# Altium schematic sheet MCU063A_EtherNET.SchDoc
size 431 x 279 mm; Date: Not shown in title block; ApprovedBy: Not shown in title block; CheckedBy: Not shown in title block; Author: Not shown in title block; CompanyName: Not shown in title block; Engineer: Not shown in title block; Organization: Not shown in title block; Address1: Not shown in title block; Address2: Not shown in title block; Address3: Not shown in title block; Address4: Not shown in title block; DocumentNumber: 7; Revision: Use project parameter SCH_Rev; SheetNumber: 7; SheetTotal: 11; PageSetup: Record=PageOptions¦CenterHorizontal=True¦CenterVertical=True¦PrintScale=1.00¦XCorrection=1.00¦YCorrection=1.00¦PrintKind=0¦BorderSize=5000000¦LeftOffset=0¦BottomOffset=0¦Orientation=2¦PaperLength=1000¦PaperWidth=1000¦Scale=100¦PaperSource=15¦PrintQuality=600¦MediaType=1¦DitherType=10¦PaperKind=Letter¦PrintScaleMode=1
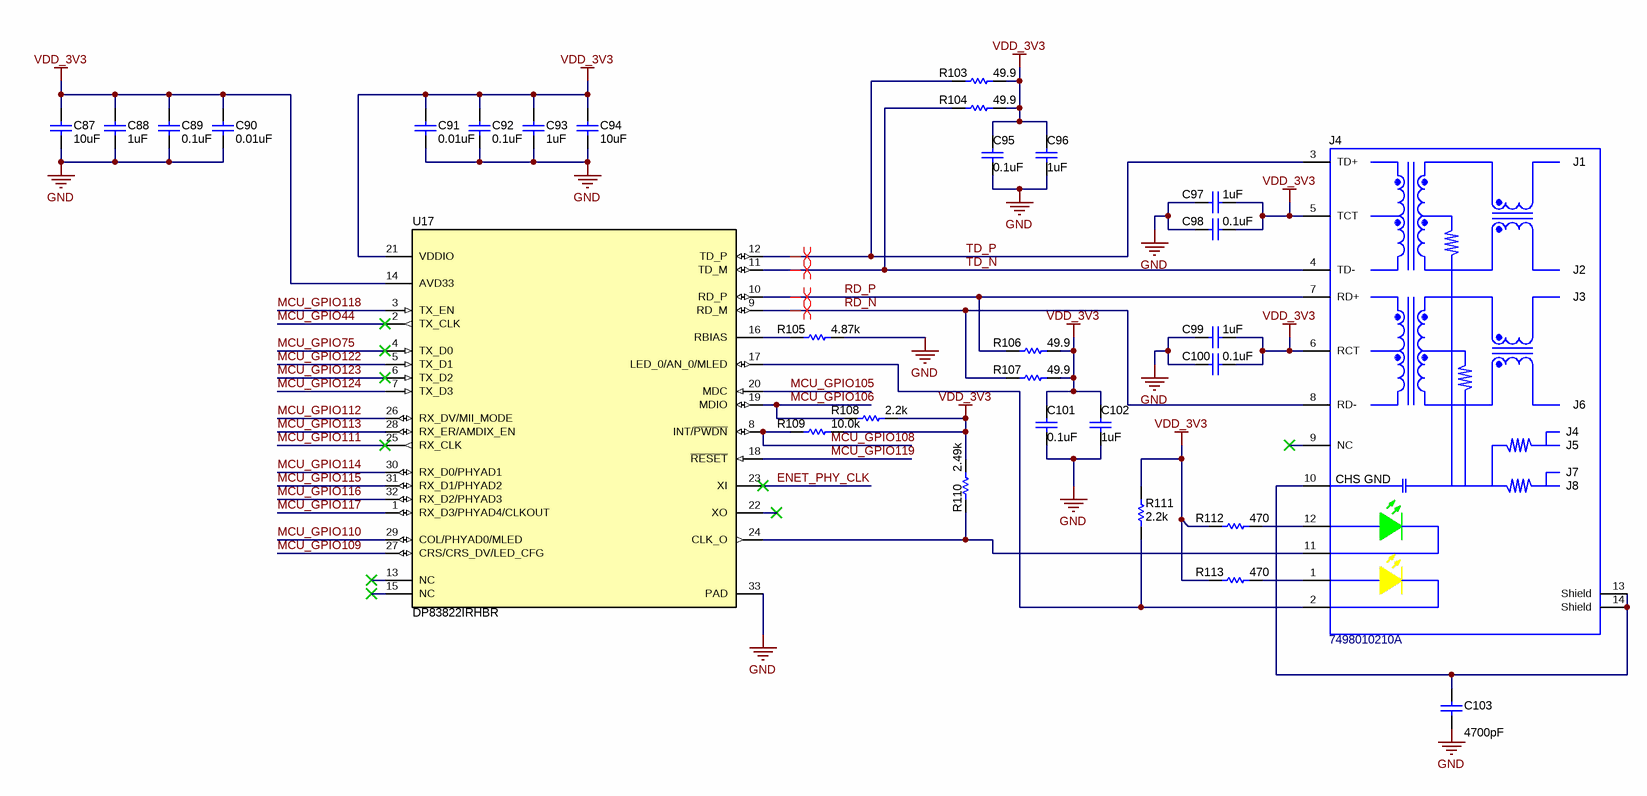
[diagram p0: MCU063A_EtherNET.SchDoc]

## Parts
C87  ValueDisplayed: 10uF  [0402]  (hidden comment: CL05A106MQ5NUNC)
C88  ValueDisplayed: 1uF  [0402]  (hidden comment: EMK105BJ105KVHF)
C89  ValueDisplayed: 0.1uF  [0402]  (hidden comment: LMK105BJ104KV-F)
C90  ValueDisplayed: 0.01uF  [0402]  (hidden comment: 885012205031)
C91  ValueDisplayed: 0.01uF  [0402]  (hidden comment: 885012205031)
C92  ValueDisplayed: 0.1uF  [0402]  (hidden comment: LMK105BJ104KV-F)
C93  ValueDisplayed: 1uF  [0402]  (hidden comment: EMK105BJ105KVHF)
C94  ValueDisplayed: 10uF  [0402]  (hidden comment: CL05A106MQ5NUNC)
C95  ValueDisplayed: 0.1uF  [0402]  (hidden comment: LMK105BJ104KV-F)
C96  ValueDisplayed: 1uF  [0402]  (hidden comment: EMK105BJ105KVHF)
C97  ValueDisplayed: 1uF  [0402]  (hidden comment: EMK105BJ105KVHF)
C98  ValueDisplayed: 0.1uF  [0402]  (hidden comment: LMK105BJ104KV-F)
C99  ValueDisplayed: 1uF  [0402]  (hidden comment: EMK105BJ105KVHF)
C100  ValueDisplayed: 0.1uF  [0402]  (hidden comment: LMK105BJ104KV-F)
C101  ValueDisplayed: 0.1uF  [0402]  (hidden comment: LMK105BJ104KV-F)
C102  ValueDisplayed: 1uF  [0402]  (hidden comment: EMK105BJ105KVHF)
C103  ValueDisplayed: 4700pF  [1206]  (hidden comment: 12061C472KAT2A)
J4  7498010210A  [Wurth_7498010210A]
R103  ValueDisplayed: 49.9  [0402]  (hidden comment: RC0402FR-0749R9L)
R104  ValueDisplayed: 49.9  [0402]  (hidden comment: RC0402FR-0749R9L)
R105  ValueDisplayed: 4.87k  [0402]  (hidden comment: CRCW04024K87FKED)
R106  ValueDisplayed: 49.9  [0402]  (hidden comment: RC0402FR-0749R9L)
R107  ValueDisplayed: 49.9  [0402]  (hidden comment: RC0402FR-0749R9L)
R108  ValueDisplayed: 2.2k  [0402]  (hidden comment: CRCW04022K20JNED)
R109  ValueDisplayed: 10.0k  [0402]  (hidden comment: RC0402FR-0710KL)
R110  ValueDisplayed: 2.49k  [0402]  (hidden comment: CRCW04022K49FKED)
R111  ValueDisplayed: 2.2k  [0402]  (hidden comment: CRCW04022K20JNED)
R112  ValueDisplayed: 470  [0603]  (hidden comment: CRCW0603470RJNEA)
R113  ValueDisplayed: 470  [0603]  (hidden comment: CRCW0603470RJNEA)
U17  DP83822IRHBR  [RHB0032B]

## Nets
GND: C87.2 C88.2 C89.2 C90.2 C91.2 C92.2 C93.2 C94.2 C95.2 C96.2 C97.1 C98.1 C99.1 C100.1 C101.2 C102.2 C103.1 R105.2 U17.33(PAD)
VDD_3V3: C87.1 C88.1 C89.1 C90.1 C91.1 C92.1 C93.1 C94.1 C95.1 C96.1 C97.2 C98.2 C99.2 C100.2 C101.1 C102.1 J4.5(TCT) J4.6(RCT) R103.2 R104.2 R106.2 R107.2 R108.1 R109.2 R110.2 R111.2 R112.1 R113.1 U17.14(AVD33) U17.21(VDDIO)
ENET_PHY_CLK: U17.23(XI)
MCU_GPIO44: U17.2(TX_CLK)
MCU_GPIO75: U17.4(TX_D0)
MCU_GPIO105: U17.20(MDC)
MCU_GPIO106: R108.2 U17.19(MDIO)
MCU_GPIO108: R109.1 U17.8(INT/~{PWDN})
MCU_GPIO109: U17.27(CRS/CRS_DV/LED_CFG)
MCU_GPIO110: U17.29(COL/PHYAD0/MLED)
MCU_GPIO111: U17.25(RX_CLK)
MCU_GPIO112: U17.26(RX_DV/MII_MODE)
MCU_GPIO113: U17.28(RX_ER/AMDIX_EN)
MCU_GPIO114: U17.30(RX_D0/PHYAD1)
MCU_GPIO115: U17.31(RX_D1/PHYAD2)
MCU_GPIO116: U17.32(RX_D2/PHYAD3)
MCU_GPIO117: U17.1(RX_D3/PHYAD4/CLKOUT)
MCU_GPIO118: U17.3(TX_EN)
MCU_GPIO119: U17.18(~{RESET})
MCU_GPIO122: U17.5(TX_D1)
MCU_GPIO123: U17.6(TX_D2)
MCU_GPIO124: U17.7(TX_D3)
RD_N: J4.8(RD-) R107.1 U17.9(RD_M)
RD_P: J4.7(RD+) R106.1 U17.10(RD_P)
TD_N: J4.4(TD-) R104.1 U17.11(TD_M)
TD_P: J4.3(TD+) R103.1 U17.12(TD_P)
NetC103_2: C103.2 J4.10(CHS_GND) J4.13(Shield) J4.14(Shield)
NetJ4_1: J4.1(RIGHT_LED_ANODE) R113.2
NetJ4_2: J4.2(RIGHT_LED_CATHODE) R111.1 U17.17(LED_0/AN_0/MLED)
NetJ4_11: J4.11(LEFT_LED_CATHODE) R110.1 U17.24(CLK_O)
NetJ4_12: J4.12(LEFT_LED_ANODE) R112.2
NetR105_1: R105.1 U17.16(RBIAS)

Not connected (* = marked no-connect by the designer): J4 9(NC)*; U17 13(NC)* 15(NC)* 22(XO)*

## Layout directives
differential pair: RD_N, RD_P, TD_N, TD_P

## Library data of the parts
C87 C94 = CMP-0006340-2: CAP, CERM, 10 uF, 6.3 V, +/- 20%, X5R, 0402; Manufacturer: Samsung Electro-Mechanics; TaMin_C: -55°C; Polarized: N; SizeAreaWB_mm2: 3; Value1: Unknown; U/M: EA; Value: 10uF; TaMax_C: 85°C; SizeZ_mm: 0.6; SizeX_mm: 1; SizeY_mm: 0.5; Value2: 6.3V; Cap_F: 10µF; AEC Category: Q200
C88 C93 C96 C97 C99 C102 = CMP-0006347-2: CAP, CERM, 1 uF, 16 V, +/- 10%, X5R, 0402; Manufacturer: Taiyo Yuden; TaMin_C: -55°C; Polarized: N; SizeAreaWB_mm2: 3; Value1: Unknown; U/M: EA; Value: 1uF; TaMax_C: 85°C; SizeZ_mm: 0.6; SizeX_mm: 1; SizeY_mm: 0.5; Value2: 16V; Cap_F: 1µF; AEC Category: Q200
C89 C92 C95 C98 C100 C101 = CMP-0064930-2: CAP, CERM, 0.1 uF, 10 V,+/- 10%, X5R, 0402; Manufacturer: Taiyo Yuden; TaMin_C: -55°C; Polarized: N; SizeAreaWB_mm2: 3; Value1: Unknown; U/M: EA; Value: 0.1uF; TaMax_C: 85°C; SizeZ_mm: 0.6; SizeX_mm: 1; SizeY_mm: 0.5; Value2: 10V; Cap_F: 100nF; AEC Category: Q200
C90 C91 = CMP-0006227-2: CAP, CERM, 0.01 uF, 16 V, +/- 10%, X7R, 0402; Manufacturer: Wurth Elektronik; TaMin_C: -55°C; Polarized: N; SizeAreaWB_mm2: 3; Value1: Unknown; U/M: EA; Value: 0.01uF; TaMax_C: 125°C; SizeZ_mm: 0.6; SizeX_mm: 1; SizeY_mm: 0.5; Value2: 16V; Cap_F: 10nF; AEC Category: Q200
C103 = CMP-0008501-2: CAP, CERM, 4700 pF, 100 V, +/- 10%, X7R, 1206; Manufacturer: AVX; TaMin_C: -55°C; ESR_ohm: 1.78d; Polarized: N; SizeAreaWB_mm2: 10.92; Value1: 0.178 ohm; U/M: EA; Value: 4700pF; TaMax_C: 125°C; SizeZ_mm: 1.35; SizeX_mm: 3.2; SizeY_mm: 1.6; Value2: 100V; SizeArea_mm2: 5.12; Cap_F: 4.7nF; AEC Category: Q200
J4 = CMP-0086350-1: Connector, RJ45, 1x1, Gold, R/A, SMT; Manufacturer: Wurth Elektronik; Row_Count: 1; Gender: Female
R103 R104 R106 R107 = CMP-0026738-1: RES, 49.9, 1%, 0.063 W, 0402; Manufacturer: Yageo America; Power_W: 63mW; TempCo: 100 ppm/C; Value_Code: 49R9; U/M: EA; Value: 49.9; EIA_Code: E96; SizeX_mm: 1; SizeY_mm: 0.5; SizeZ_mm: 0.6; Value2: 0.063W; AEC Qualified: N; VDC_V: 50V; AEC Category: Q200
R105 = CMP-0026413-2: RES, 4.87 k, 1%, 0.063 W, AEC-Q200 Grade 0, 0402; Manufacturer: Vishay-Dale; Power_W: 63mW; TempCo: 100 ppm/C; Value_Code: 4k87; Value: 4.87k; EIA_Code: E96; SizeX_mm: 1; SizeY_mm: 0.5; SizeZ_mm: 0.6; Value2: 0.063W; AEC Qualified: Y; VDC_V: 50V; AEC Category: Q200; AEC Grade: 0
R108 R111 = CMP-0026890-5: RES, 2.2 k, 5%, 0.063 W, AEC-Q200 Grade 0, 0402; Manufacturer: Vishay-Dale; Power_W: 63mW; TempCo: 200 ppm/C; Value_Code: 2k20; Value: 2.2k; EIA_Code: E24; SizeX_mm: 1; SizeY_mm: 0.5; SizeZ_mm: 0.6; Value2: 0.063W; AEC Qualified: Y; VDC_V: 50V; AEC Category: Q200; AEC Grade: 0
R109 = CMP-0078669-1: RES, 10.0 k, 1%, 0.063 W, 0402; Manufacturer: Yageo America; Power_W: 63mW; Green_Lifecycle: Active; TempCo: 100 ppm/C; Value_Code: 10k0; Green_REACh: Passed; Value: 10.0k; EIA_Code: E96; Res_ohm: 10k; SizeX_mm: 1; SizeY_mm: 0.5; SizeZ_mm: 0.6; Value2: 0.063W; AEC Qualified: N; AEC Category: Q200
R110 = CMP-0026237-2: RES, 2.49 k, 1%, 0.063 W, AEC-Q200 Grade 0, 0402; Manufacturer: Vishay-Dale; Power_W: 63mW; TempCo: 100 ppm/C; Value_Code: 2k49; Value: 2.49k; EIA_Code: E96; SizeX_mm: 1; SizeY_mm: 0.5; SizeZ_mm: 0.6; Value2: 0.063W; AEC Qualified: Y; VDC_V: 50V; AEC Category: Q200; AEC Grade: 0
R112 R113 = CMP-0025813-4: RES, 470, 5%, 0.1 W, AEC-Q200 Grade 0, 0603; Manufacturer: Vishay-Dale; Power_W: 100mW; TempCo: 200 ppm/C; Value_Code: 470R; Value: 470; EIA_Code: E24; SizeX_mm: 1.6; SizeY_mm: 0.8; SizeZ_mm: 1; Value2: 0.1W; SizeArea_mm2: 1.28; AEC Qualified: Y; VDC_V: 75V; AEC Category: Q200; AEC Grade: 0
U17 = CMP-0076010-3: Robust, Low Power 10/100 Ethernet Physical Layer Transceiver, RHB0032B (VQFN-32); Alternate PartNumber: DP83822IRHBT; Manufacturer: Texas Instruments; SizeZ_mm: 1.0; SizeX_mm: 5.0; SizeArea_mm2: 25.0; CompType: IC; SizeAreaWB_mm2: 49.0; AEC Category: Q200; AEC Qualified: N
